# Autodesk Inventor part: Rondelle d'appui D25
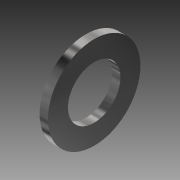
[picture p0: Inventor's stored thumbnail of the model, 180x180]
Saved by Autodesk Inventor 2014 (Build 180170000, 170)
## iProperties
Created: 2015-09
Part Number: Rondelle d'appui D25
Material: Générique
Document SubType Name: Modeling
Designer: OL
Density: 1 g/cm^3
Appearance: Par défaut
Author: OL
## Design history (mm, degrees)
sketch "Esquisse1"
  geometry: C1 r 22 at (0, 0); C2 r 12.5 at (0, 0); 1 further point
  constraints: 2 centre point, 2 coincident
  dimensions: "d0" = 25 diameter of C2; "d3" = 44 diameter of C1
extrude "Extrusion1" new body sketch "Esquisse1" distance "d4" = 4; taper "d5" = 0 deg
node "Solide1"
